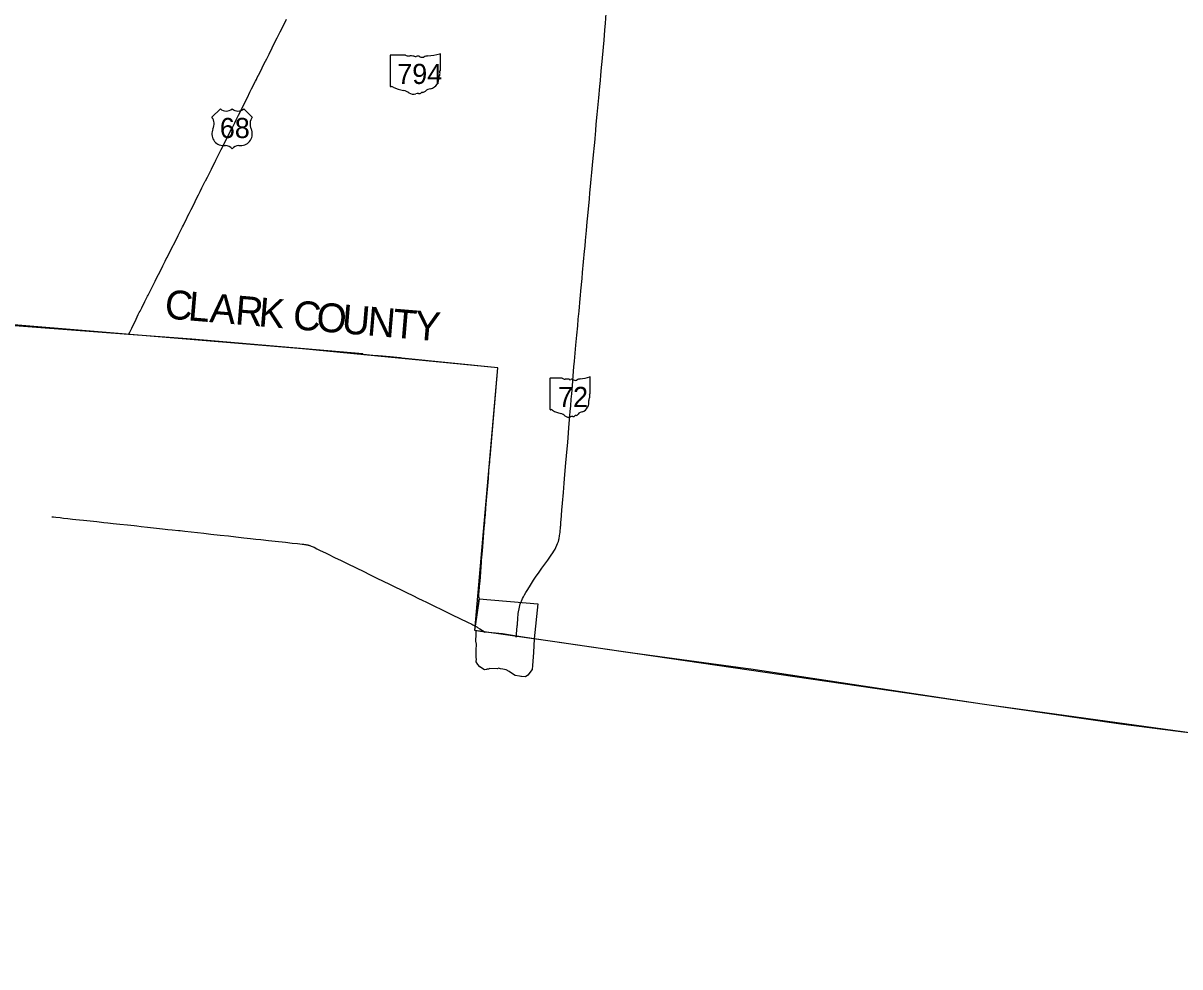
# Model space of a CAD drawing. Extents: x 0 to 34, y 0 to 22.
# Drawn here: x 6.689 to 7.332, y 15.177 to 15.702 of the extents above; entities that cross this region are included whole.
import ezdxf

# ---------------------------------------------------------------- set-up
doc = ezdxf.new("R2010")
doc.units = 0
for name, color, linetype in [('GM_X_Corporation', 7, 'Continuous'), ('GM_X_County', 7, 'Continuous'), ('GM_X_County_Text', 7, 'Continuous'), ('GM_X_State_Location', 7, 'Continuous'), ('GM_X_State_Route', 7, 'Continuous'), ('GM_X_State_Shield', 7, 'Continuous'), ('GM_X_US_Location', 7, 'Continuous'), ('GM_X_US_Route', 7, 'Continuous'), ('GM_X_US_Shield', 7, 'Continuous'), ('SC_Scratch1', 7, 'Continuous')]:
    doc.layers.add(name, color=color, linetype=linetype)

msp = doc.modelspace()

# ---------------------------------------------------------------- linework, layer by layer
at = {"layer": 'GM_X_Corporation'}
msp.add_lwpolyline([(6.94092, 15.36412), (6.94018, 15.36425), (6.94053, 15.36674), (6.94256, 15.3819), (6.97508, 15.37907), (6.97314, 15.35969), (6.97264, 15.35214), (6.97214, 15.3449), (6.97199, 15.34266), (6.96953, 15.3395), (6.96827, 15.33857), (6.96597, 15.3387), (6.96561, 15.33872), (6.96495, 15.33889), (6.96249, 15.33934), (6.96042, 15.34063), (6.95917, 15.34146), (6.95762, 15.34249), (6.95569, 15.34283), (6.95437, 15.34305), (6.95389, 15.34317), (6.95347, 15.34329), (6.95257, 15.34296), (6.94848, 15.34322), (6.94767, 15.34286), (6.94682, 15.34274), (6.94666, 15.34272), (6.9455, 15.34243), (6.94296, 15.34407), (6.94171, 15.34542), (6.94079, 15.34691), (6.94095, 15.34864), (6.94093, 15.34902), (6.94076, 15.35204), (6.94086, 15.35344), (6.94109, 15.35666), (6.94071, 15.35832), (6.94075, 15.35954), (6.94081, 15.36123)], close=True, dxfattribs=at)
at = {"layer": 'GM_X_County'}
msp.add_lwpolyline([(7.34025, 15.30712), (7.33115, 15.30812), (7.2994, 15.3122), (7.22227, 15.32333), (7.09366, 15.34277), (7.09059, 15.34316), (7.02384, 15.35225), (6.97314, 15.35969), (6.96321, 15.36115), (6.95545, 15.36239), (6.9477, 15.36324), (6.94575, 15.36348), (6.94092, 15.36412), (6.94018, 15.36425), (6.94053, 15.36674), (6.94264, 15.38187), (6.94246, 15.38267), (6.94242, 15.38293), (6.94238, 15.38321), (6.94236, 15.38346), (6.94236, 15.38398), (6.94238, 15.38477), (6.94247, 15.38608), (6.9427, 15.38871), (6.94301, 15.39185), (6.94319, 15.39395), (6.94342, 15.3971), (6.94355, 15.39946), (6.94378, 15.4021), (6.9439, 15.40339), (6.94416, 15.40682), (6.9443, 15.4087), (6.94451, 15.41105), (6.94495, 15.416), (6.94538, 15.42124), (6.94565, 15.42439), (6.94575, 15.4256), (6.94598, 15.42859), (6.94629, 15.43226), (6.94649, 15.43463), (6.94666, 15.43673), (6.94765, 15.44881), (6.94798, 15.45301), (6.94814, 15.45537), (6.94837, 15.458), (6.9485, 15.45958), (6.94852, 15.46011), (6.94853, 15.46022), (6.94855, 15.46037), (6.94855, 15.46045), (6.94856, 15.46054), (6.94856, 15.46061), (6.95286, 15.51046), (6.89959, 15.51574), (6.89916, 15.51581), (6.89876, 15.51587), (6.89665, 15.51608), (6.89297, 15.51643), (6.88875, 15.51681), (6.88638, 15.51702), (6.88348, 15.51725), (6.87979, 15.51756), (6.87914, 15.51761), (6.87887, 15.51764), (6.87848, 15.5177), (6.87822, 15.51776), (6.87809, 15.5178), (6.87797, 15.51787), (6.87786, 15.51799), (6.87778, 15.51809), (6.7827, 15.52641), (6.74756, 15.52897), (6.71333, 15.53157), (6.67682, 15.53438)], dxfattribs=at)
at = {"layer": 'GM_X_State_Route'}
msp.add_line((6.96317, 15.3606), (6.96323, 15.36111), dxfattribs=at)
for points in [[(7.0109, 15.68081), (7.0116, 15.68863), (7.012, 15.69256), (7.01247, 15.69808), (7.01278, 15.70202), (7.01292, 15.70466), (7.01305, 15.70756), (7.01313, 15.71283), (7.01313, 15.71652), (7.01321, 15.72074), (7.01332, 15.72311), (7.01359, 15.72705), (7.0141, 15.7331), (7.01445, 15.73756), (7.01527, 15.74729), (7.01543, 15.74992), (7.01554, 15.75282), (7.01556, 15.75414), (7.01551, 15.75652), (7.01533, 15.76169)], [(6.98782, 15.42225), (6.98784, 15.42253), (6.98801, 15.4247), (6.98809, 15.42575), (6.98856, 15.43127), (6.9889, 15.43521), (6.98938, 15.44099), (6.9898, 15.44625), (6.99001, 15.44861), (6.99042, 15.45334), (6.99077, 15.45755), (6.99112, 15.46148), (6.99177, 15.4691), (6.99195, 15.47147), (6.99241, 15.47699), (6.99278, 15.48172), (6.99316, 15.48618), (6.99345, 15.48933), (6.99375, 15.49301), (6.99399, 15.4959), (6.99437, 15.50037), (6.99482, 15.50589), (6.99525, 15.51088), (6.99551, 15.51403), (6.99631, 15.52296), (6.99683, 15.52847), (6.99732, 15.53372), (6.99764, 15.5374), (6.99806, 15.54186), (6.99872, 15.54895), (6.99886, 15.55068), (6.99907, 15.55316), (6.99971, 15.55998), (7.00003, 15.56339), (7.00114, 15.57521), (7.00138, 15.57808), (7.00167, 15.58125), (7.0022, 15.58676), (7.00263, 15.59148), (7.00281, 15.59332), (7.00347, 15.60041), (7.00383, 15.60435), (7.00413, 15.60776), (7.00445, 15.61117), (7.00485, 15.61537), (7.00499, 15.61721), (7.00516, 15.61905), (7.00554, 15.62299), (7.00609, 15.62876), (7.00658, 15.63401), (7.00693, 15.63761), (7.00696, 15.63795), (7.00714, 15.64005), (7.00735, 15.64241), (7.00767, 15.64583), (7.00817, 15.65134), (7.00903, 15.66053), (7.00959, 15.66683), (7.00993, 15.67024), (7.01018, 15.67313), (7.01057, 15.67733), (7.0109, 15.68081)], [(6.70498, 15.42761), (6.70584, 15.42751), (6.70703, 15.42737), (6.70943, 15.42708), (6.71145, 15.42685), (6.7137, 15.42658), (6.71647, 15.42631), (6.71826, 15.42613), (6.72035, 15.42594), (6.72245, 15.4257), (6.72985, 15.42484), (6.73383, 15.42438), (6.73596, 15.42413), (6.73894, 15.42381), (6.74261, 15.42343), (6.74691, 15.423), (6.75063, 15.42262), (6.75215, 15.42246), (6.75461, 15.42217), (6.75813, 15.4218), (6.76315, 15.42125), (6.76635, 15.42091), (6.76939, 15.42057), (6.7718, 15.42031), (6.77536, 15.41993), (6.77621, 15.41984), (6.77882, 15.41955), (6.78239, 15.41914), (6.78936, 15.41837), (6.79329, 15.41796), (6.79843, 15.41741), (6.80315, 15.41688), (6.80728, 15.4164), (6.81163, 15.41593), (6.8153, 15.41551), (6.81834, 15.41517), (6.82117, 15.41486), (6.82531, 15.4144), (6.82903, 15.41402), (6.8348, 15.41337), (6.83846, 15.41296), (6.84145, 15.41261), (6.84412, 15.41233), (6.84477, 15.41226), (6.84537, 15.41219), (6.84576, 15.41214), (6.84614, 15.41209), (6.84654, 15.41203), (6.84687, 15.41197), (6.84718, 15.41191), (6.84747, 15.41184), (6.84779, 15.41175), (6.84811, 15.41166), (6.84844, 15.41156), (6.84881, 15.41142), (6.84918, 15.41127), (6.84967, 15.41106), (6.85015, 15.41084), (6.85068, 15.4106), (6.85234, 15.40979), (6.85413, 15.40889), (6.85704, 15.40747), (6.85855, 15.40674), (6.86209, 15.40499), (6.86573, 15.40319), (6.86867, 15.40178), (6.87446, 15.39896), (6.87801, 15.39723), (6.88184, 15.39536), (6.88524, 15.39367), (6.88945, 15.3916), (6.89226, 15.39026), (6.89599, 15.38842), (6.8987, 15.38711), (6.9022, 15.3854), (6.90572, 15.38371), (6.90885, 15.38217), (6.91089, 15.38117), (6.9133, 15.38), (6.9155, 15.37891), (6.91811, 15.37763), (6.92113, 15.37615), (6.92524, 15.37413), (6.92832, 15.37264), (6.93108, 15.37132), (6.93316, 15.37034), (6.93447, 15.36971), (6.93566, 15.36915), (6.93684, 15.36859), (6.93779, 15.36814), (6.93845, 15.36781), (6.93903, 15.36753), (6.9397, 15.36718), (6.94054, 15.3667)], [(6.96565, 15.37977), (6.96567, 15.37982), (6.96602, 15.38064), (6.96666, 15.38208), (6.96712, 15.38303), (6.96775, 15.38418), (6.96855, 15.38554), (6.96954, 15.3871), (6.97107, 15.38956), (6.97274, 15.39225), (6.9739, 15.394), (6.97584, 15.39683), (6.97737, 15.39898), (6.98064, 15.40344), (6.98262, 15.40624), (6.98352, 15.40755), (6.98408, 15.40845), (6.98473, 15.4096), (6.98524, 15.41055), (6.98576, 15.41174), (6.98615, 15.41272), (6.98655, 15.41383), (6.98668, 15.41425), (6.98674, 15.41448), (6.98686, 15.41491), (6.98698, 15.41553), (6.98723, 15.41687), (6.98741, 15.41812), (6.98749, 15.41884), (6.98762, 15.41999), (6.98771, 15.42095), (6.98782, 15.42225)], [(6.96323, 15.36111), (6.96335, 15.36244), (6.96352, 15.36454), (6.96373, 15.36697), (6.96377, 15.36742), (6.96407, 15.37134), (6.96424, 15.37328), (6.96428, 15.37369), (6.96442, 15.37473), (6.96467, 15.37628), (6.96489, 15.37731), (6.9651, 15.37816), (6.9654, 15.37912), (6.96546, 15.37929), (6.96552, 15.37944), (6.96563, 15.37973), (6.96565, 15.37977)], [(6.94054, 15.3667), (6.94114, 15.36636), (6.94164, 15.36607), (6.94295, 15.36526), (6.94577, 15.36344)]]:
    msp.add_lwpolyline(points, dxfattribs=at)
at = {"layer": 'GM_X_State_Shield'}
for p, q in [((6.89302, 15.68402), (6.89302, 15.66704)), ((6.90149, 15.68431), (6.8933, 15.68431)), ((6.92099, 15.67585), (6.92099, 15.68473)), ((6.92099, 15.67585), (6.92099, 15.67585)), ((6.9819, 15.50438), (6.9819, 15.48739)), ((6.98867, 15.50467), (6.98212, 15.50467)), ((7.00428, 15.49621), (7.00428, 15.50509)), ((7.00428, 15.49621), (7.00428, 15.49621))]:
    msp.add_line(p, q, dxfattribs=at)
for centre, radius, start, end in [((6.98216, 15.50441), 0.000259, 98.1301, 188.1301), ((6.99023, 15.50664), 0.00251, 231.61951, 271.11188), ((6.99107, 15.49513), 0.00903, 80.48669, 94.98827), ((6.99312, 15.5045), 0.000725, 219.79206, 297.10237), ((6.99418, 15.50254), 0.00151, 54.46668, 119.14113), ((6.99613, 15.50523), 0.00181, 233.85621, 294.82819), ((6.99933, 15.49948), 0.00477, 97.34618, 120.76885), ((6.99631, 15.52783), 0.02373, 275.84447, 288.90645), ((7.00403, 15.50513), 0.000249, 351.86209, 97.738), ((7.00422, 15.49555), 0.000386, 107.94398, 210.33697), ((7.00177, 15.49443), 0.00231, 340.03296, 23.64957), ((7.00401, 15.49617), 0.000267, 289.60381, 7.73413), ((6.99764, 15.49136), 0.00594, 292.30889, 8.98584), ((7.00517, 15.49249), 0.00168, 136.8065, 186.92959), ((6.98216, 15.48736), 0.000262, 171.95839, 258.30661), ((6.9822, 15.48909), 0.002, 267.33899, 280.60386), ((6.98261, 15.48641), 0.00072, 29.74838, 93.27175), ((6.99169, 15.50167), 0.01714, 240.41292, 257.1985), ((6.98658, 15.47976), 0.00536, 47.18416, 75.83597), ((6.99238, 15.48633), 0.0034, 230.70037, 286.29184), ((6.99435, 15.48046), 0.0028, 85.69512, 111.20995), ((6.9946, 15.48506), 0.00181, 268.77702, 315.54927), ((6.99624, 15.48341), 0.00051, 65.75173, 132.64842), ((6.99602, 15.48575), 0.00192, 282.87319, 323.27711), ((7.00014, 15.48262), 0.00325, 94.40312, 142.57675)]:
    msp.add_arc(centre, radius, start, end, dxfattribs=at)
for centre, major_axis, start_param, end_param in [((6.89334, 15.68406), (0.000324, 0), 1.712693, 3.28349), ((6.90344, 15.68628), (0.00314, 0), 4.042523, 4.731795), ((6.90448, 15.67478), (0.01128, 0), 1.404758, 1.657858), ((6.90704, 15.68414), (0.000907, 0), 3.836095, 5.185415), ((6.90837, 15.68218), (0.00189, 0), 0.950623, 2.079405), ((6.91081, 15.68487), (0.00227, 0), 4.081561, 5.145723), ((6.91481, 15.67912), (0.00597, 0), 1.699011, 2.107814), ((6.91103, 15.70747), (0.02966, 0), 4.814394, 5.042369), ((6.92068, 15.68477), (0.000311, 0), 6.141152, 7.989035), ((6.92092, 15.6752), (0.000482, 0), 1.883978, 3.671073), ((6.92066, 15.67581), (0.000333, 0), 5.05454, 6.418171), ((6.91269, 15.671), (0.00742, 0), 5.101752, 6.440018), ((6.92211, 15.67213), (0.0021, 0), 2.387724, 3.262537), ((6.91786, 15.67407), (0.00289, 0), 5.934695, 6.695948), ((6.89334, 15.667), (0.000327, 0), 3.00124, 4.508301), ((6.89339, 15.66874), (0.00249, 0), 4.665946, 4.897461), ((6.8939, 15.66606), (0.0009, 0), 0.519207, 1.627899), ((6.90526, 15.68132), (0.02142, 0), 4.195997, 4.488961), ((6.89888, 15.65941), (0.0067, 0), 0.823519, 1.323587), ((6.90613, 15.66597), (0.00425, 0), 4.026481, 4.996735), ((6.90858, 15.6601), (0.00349, 0), 1.495662, 1.94098), ((6.90889, 15.6647), (0.00227, 0), 4.691044, 5.507374), ((6.91094, 15.66305), (0.000638, 0), 1.147584, 2.315152), ((6.91067, 15.66539), (0.0024, 0), 4.937069, 5.64225), ((6.91582, 15.66227), (0.00406, 0), 1.647645, 2.488434)]:
    msp.add_ellipse(centre, major_axis=major_axis, ratio=0.8, start_param=start_param, end_param=end_param, dxfattribs=at)
at = {"layer": 'GM_X_US_Route'}
for points in [[(6.81051, 15.65455), (6.81305, 15.65959), (6.81421, 15.66195), (6.81438, 15.6623), (6.81503, 15.6636), (6.81598, 15.66548), (6.81699, 15.6675), (6.81747, 15.66846), (6.81811, 15.66975), (6.81861, 15.67073), (6.81913, 15.67176), (6.81987, 15.6732), (6.82071, 15.67488), (6.82186, 15.67721), (6.82305, 15.67959), (6.82436, 15.68222), (6.82567, 15.68482), (6.82742, 15.68835), (6.82858, 15.69065), (6.83022, 15.69394), (6.8319, 15.69722), (6.83346, 15.70029), (6.83547, 15.70428)], [(6.78947, 15.61265), (6.79023, 15.61417), (6.79037, 15.61444), (6.7914, 15.61649), (6.79213, 15.61794), (6.79361, 15.62077), (6.79425, 15.6221), (6.7957, 15.62497), (6.7959, 15.62539), (6.79614, 15.6259), (6.79648, 15.62662), (6.79912, 15.6318), (6.80015, 15.6339), (6.80077, 15.63513), (6.80258, 15.63873), (6.80409, 15.64173), (6.80527, 15.64409), (6.80657, 15.64667), (6.8074, 15.6483), (6.80868, 15.65091), (6.81046, 15.65446), (6.81051, 15.65455)], [(6.76154, 15.55707), (6.76231, 15.5586), (6.76294, 15.55988), (6.76541, 15.56478), (6.76657, 15.56708), (6.76791, 15.56971), (6.76853, 15.57091), (6.76898, 15.57178), (6.77115, 15.57601), (6.77375, 15.58117), (6.77519, 15.58401), (6.77684, 15.58733), (6.77754, 15.58872), (6.77804, 15.5897), (6.77892, 15.59144), (6.77956, 15.59273), (6.7806, 15.59482), (6.78132, 15.59623), (6.78236, 15.59835), (6.78376, 15.60117), (6.7854, 15.60449), (6.78644, 15.60656), (6.7874, 15.60849), (6.78833, 15.61039), (6.78947, 15.61265)], [(6.7581, 15.5502), (6.75841, 15.5508), (6.76008, 15.55416), (6.76154, 15.55707)], [(6.75353, 15.54111), (6.75394, 15.54192), (6.75485, 15.54381), (6.75661, 15.5473), (6.7581, 15.5502)], [(6.74933, 15.53252), (6.74974, 15.53337), (6.75114, 15.53622), (6.75235, 15.53871), (6.75298, 15.54), (6.75353, 15.54111)], [(6.74758, 15.52892), (6.74824, 15.53028), (6.74933, 15.53252)]]:
    msp.add_lwpolyline(points, dxfattribs=at)
at = {"layer": 'GM_X_US_Shield'}
for p, q in [((6.79859, 15.65448), (6.79393, 15.64982)), ((6.8163, 15.64982), (6.81164, 15.65448)), ((6.80045, 15.63397), (6.80139, 15.63397)), ((6.80884, 15.63397), (6.80978, 15.63397))]:
    msp.add_line(p, q, dxfattribs=at)
for centre, radius, start, end in [((6.78858, 15.64607), 0.00653, 334.54712, 35.00093), ((6.80185, 15.65781), 0.00466, 225.573, 314.427), ((6.80838, 15.65781), 0.00466, 225.573, 314.427), ((6.82165, 15.64607), 0.00653, 144.99907, 205.45288), ((6.80038, 15.64049), 0.00653, 154.83192, 270.63826), ((6.80985, 15.64049), 0.00653, 269.36174, 25.16808), ((6.80139, 15.62931), 0.00466, 36.8699, 90), ((6.80884, 15.62931), 0.00466, 90, 143.1301)]:
    msp.add_arc(centre, radius, start, end, dxfattribs=at)
at = {"layer": 'SC_Scratch1'}
msp.add_lwpolyline([(8.38743, 16.58942), (8.34724, 16.43572), (8.31639, 16.31846), (8.25319, 16.08617), (8.22885, 15.99128), (8.18498, 15.80071), (8.14361, 15.64612), (8.07834, 15.39161), (8.02497, 15.17727), (7.75816, 15.20795), (7.75969, 15.21984), (7.72807, 15.22284), (7.48332, 15.24924), (7.34777, 15.26186), (7.34025, 15.30712), (7.2249, 15.32295), (6.98582, 15.35783), (6.94018, 15.36425), (6.95286, 15.51046), (6.84427, 15.52102), (6.47407, 15.55166)], dxfattribs=at)

# ---------------------------------------------------------------- texts
at = {"layer": 'GM_X_County_Text'}
for s, rotation, p in [('C', 355.19505, (6.76723, 15.53794)), ('L', 355.19525, (6.78027, 15.53685)), ('A', 355.19545, (6.79225, 15.53584)), ('R', 355.19505, (6.80641, 15.53465)), ('K', 355.19518, (6.81945, 15.53355)), ('C', 355.19505, (6.83848, 15.53195)), ('O', 355.19545, (6.85152, 15.53086)), ('U', 355.19518, (6.86569, 15.52967)), ('N', 355.19518, (6.87985, 15.52848)), ('T', 355.19525, (6.89402, 15.52729)), ('Y', 355.19518, (6.906, 15.52628))]:
    msp.add_text(s, height=0.01607, rotation=rotation, dxfattribs=at).set_placement(p)
at = {"layer": 'GM_X_State_Location'}
for s, p in [('794', (6.90102, 15.67323)), ('72', (6.98879, 15.49359))]:
    msp.add_text(s, height=0.0000161, rotation=0.00001, dxfattribs=at).set_placement(p)
for s, p in [('s', (6.90669, 15.6744)), ('r', (6.90669, 15.6744)), ('s', (6.99284, 15.49476)), ('r', (6.99284, 15.49476))]:
    msp.add_text(s, height=0.0000161, dxfattribs=at).set_placement(p)
at = {"layer": 'GM_X_State_Shield'}
for s, p in [('794', (6.89697, 15.66823)), ('72', (6.98641, 15.48859))]:
    msp.add_text(s, height=0.011189, dxfattribs=at).set_placement(p)
at = {"layer": 'GM_X_US_Location'}
for s in ['0', '/']:
    msp.add_text(s, height=0.0000161, dxfattribs=at).set_placement((6.80511, 15.64367))
msp.add_text('68', height=0.0000161, rotation=0.00001, dxfattribs=at).set_placement((6.80179, 15.64034))
at = {"layer": 'GM_X_US_Shield'}
msp.add_text('68', height=0.011189, dxfattribs=at).set_placement((6.79831, 15.63816))

doc.saveas('drawing.dxf')
